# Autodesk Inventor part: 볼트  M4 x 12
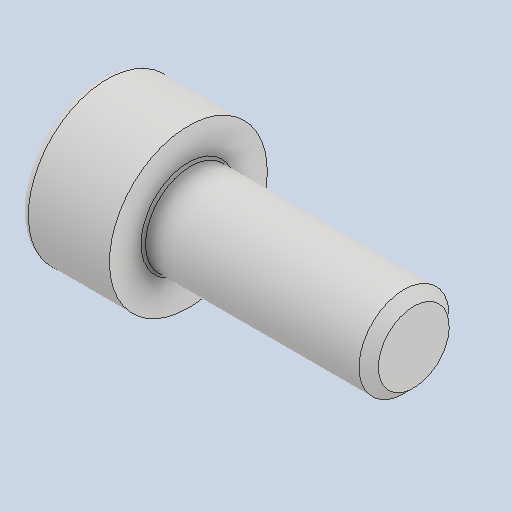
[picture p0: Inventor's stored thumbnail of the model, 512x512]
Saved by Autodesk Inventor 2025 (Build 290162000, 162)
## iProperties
Created: 2024-08
Part Number: 볼트  M4 x 12
Material: 스테인리스강
Description: 6각머리 태핑 나사
Document SubType Name: Modeling
Designer: SAMSUNG
Density: 8.08 g/cm^3
Appearance: 기본값
Sending System: Autodesk Inventor 2025
Preprocessor: ST-DEVELOPER v20
Author: jhkim
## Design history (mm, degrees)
feature "Solid1"
node "솔리드1"
